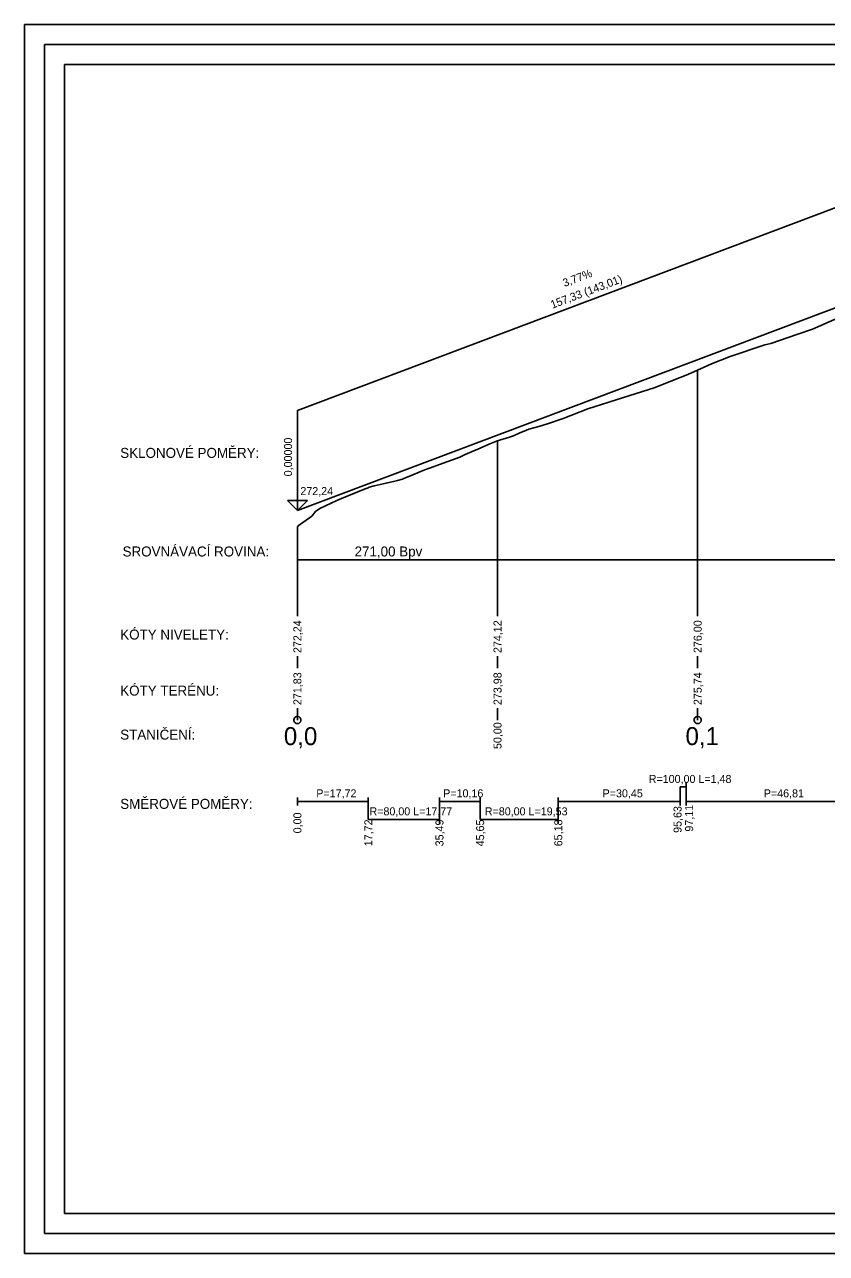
# Model space of a CAD drawing. Extents: x -761995 to -761565, y -1048251 to -1047944.
# Drawn here: x -761994.5 to -761794.2, y -1048251.1 to -1047944.1 of the extents above; entities that cross this region are included whole.
import ezdxf

# ---------------------------------------------------------------- set-up
doc = ezdxf.new("R2010")
doc.units = 0
for name, color, linetype in [('C3D-PROFIL-NIVELETA', 7, 'Continuous'), ('C3D-PROFIL-POPIS', 7, 'Continuous'), ('C3D-PROFIL-POPIS-NIVELETA', 7, 'Continuous'), ('C3D-PROFIL-TEREN', 7, 'Continuous'), ('C3D-ZOBPROF-OSY-NADPIS', 7, 'Continuous'), ('C3D-ZOBPROF-PROUZEK-NAVRH', 7, 'Continuous'), ('C3D-ZOBPROF-PROUZEK-POPIS', 7, 'Continuous'), ('C3D-ZOBPROF-PROUZEK-TEREN', 7, 'Continuous'), ('C3D-ZOBPROF-RASTR-VERHL', 7, 'Continuous'), ('C3D-ZOBPROF-RASTR-VERVEDL', 7, 'Continuous'), ('C3D-ZOBPROF-SROV-ROVINA', 7, 'Continuous'), ('Default', 7, 'Continuous'), ('U_formát', 7, 'Continuous'), ('U_rozvržení_rámeček', 7, 'Continuous')]:
    doc.layers.add(name, color=color, linetype=linetype)

# ---------------------------------------------------------------- blocks, each defined once
blk = doc.blocks.new('PP-sipka')
at = {"layer": 'Default'}
for p, q in [((0, 0), (-4, 4)), ((-4, 4), (4, 4)), ((4, 4), (0, 0))]:
    blk.add_line(p, q, dxfattribs=at)
blk = doc.blocks.new('U1096')
at = {"layer": 'Default'}
for p, q in [((-420, 0), (-420, -10)), ((-420, -297), (-420, -287)), ((-420, -297), (-410, -297))]:
    blk.add_line(p, q, dxfattribs=at)
blk.add_lwpolyline([(0, -297), (0, 0), (-420, 0), (-420, -297)], close=True, dxfattribs=at)
at = {"layer": 'U_formát'}
for points in [[(-425, 5), (5, 5), (5, -302), (-425, -302)], [(-5, -292), (-5, -5), (-415, -5), (-415, -292)]]:
    blk.add_lwpolyline(points, close=True, dxfattribs=at)

msp = doc.modelspace()

# ---------------------------------------------------------------- linework, layer by layer
at = {"layer": 'C3D-PROFIL-NIVELETA'}
msp.add_lwpolyline([(-761926.36, -1048065.48), (-761783.34, -1048011.62)], dxfattribs=at)
at = {"layer": 'C3D-PROFIL-POPIS'}
msp.add_line((-761926.36, -1048069.55), (-761926.36, -1048077.86), dxfattribs=at)
at = {"layer": 'C3D-PROFIL-POPIS-NIVELETA'}
for p, q in [((-761926.36, -1048040.48), (-761783.34, -1047986.62)), ((-761926.36, -1048065.48), (-761926.36, -1048040.48))]:
    msp.add_line(p, q, dxfattribs=at)
at = {"layer": 'C3D-PROFIL-TEREN'}
msp.add_lwpolyline([(-761926.36, -1048069.55), (-761926.16, -1048069.35), (-761922.76, -1048066.89), (-761921.82, -1048065.73), (-761920.76, -1048064.98), (-761916.48, -1048063.02), (-761915.33, -1048062.49), (-761909.4, -1048060.11), (-761908.64, -1048059.81), (-761908.38, -1048059.71), (-761907.2, -1048059.3), (-761906.42, -1048059.13), (-761904.2, -1048058.64), (-761901.97, -1048058.15), (-761901.31, -1048058.01), (-761900.08, -1048057.65), (-761899.75, -1048057.51), (-761897.53, -1048056.57), (-761895.97, -1048055.92), (-761895.31, -1048055.66), (-761894.09, -1048055.18), (-761893.09, -1048054.81), (-761890.87, -1048054.01), (-761885.78, -1048052.18), (-761884.4, -1048051.51), (-761880.71, -1048049.91), (-761878.26, -1048048.86), (-761876.63, -1048048.16), (-761875.82, -1048047.9), (-761873.38, -1048047.14), (-761872.38, -1048046.83), (-761870.94, -1048046.2), (-761869.1, -1048045.39), (-761868.5, -1048045.21), (-761866.06, -1048044.48), (-761863.62, -1048043.74), (-761862.65, -1048043.43), (-761861.18, -1048042.95), (-761859.95, -1048042.54), (-761853.82, -1048040.09), (-761843.28, -1048036.77), (-761837.24, -1048034.82), (-761830.73, -1048032.24), (-761829.25, -1048031.66), (-761827.27, -1048030.88), (-761822.86, -1048028.88), (-761818.23, -1048027.06), (-761809.61, -1048024.11), (-761808.06, -1048023.76), (-761801.56, -1048021.51), (-761797.68, -1048020.19), (-761791.41, -1048017.48)], dxfattribs=at)
at = {"layer": 'C3D-ZOBPROF-PROUZEK-NAVRH'}
for p, q in [((-761830.73, -1048138.16), (-761830.73, -1048134.56)), ((-761830.73, -1048134.56), (-761829.25, -1048134.56)), ((-761829.25, -1048135.56), (-761829.25, -1048133.56)), ((-761829.25, -1048134.56), (-761829.25, -1048138.16)), ((-761926.36, -1048139.16), (-761926.36, -1048137.16)), ((-761908.64, -1048139.16), (-761908.64, -1048137.16)), ((-761890.87, -1048139.16), (-761890.87, -1048137.16)), ((-761880.71, -1048139.16), (-761880.71, -1048137.16)), ((-761861.18, -1048139.16), (-761861.18, -1048137.16)), ((-761830.73, -1048139.16), (-761830.73, -1048137.16)), ((-761829.25, -1048139.16), (-761829.25, -1048137.16)), ((-761926.36, -1048138.16), (-761908.64, -1048138.16)), ((-761908.64, -1048138.16), (-761908.64, -1048142.66)), ((-761890.87, -1048142.66), (-761890.87, -1048138.16)), ((-761890.87, -1048138.16), (-761880.71, -1048138.16)), ((-761880.71, -1048138.16), (-761880.71, -1048142.66)), ((-761861.18, -1048142.66), (-761861.18, -1048138.16)), ((-761861.18, -1048138.16), (-761830.73, -1048138.16)), ((-761829.25, -1048138.16), (-761782.44, -1048138.16)), ((-761908.64, -1048142.66), (-761890.87, -1048142.66)), ((-761890.87, -1048143.66), (-761890.87, -1048141.66)), ((-761880.71, -1048142.66), (-761861.18, -1048142.66)), ((-761861.18, -1048143.66), (-761861.18, -1048141.66))]:
    msp.add_line(p, q, dxfattribs=at)
at = {"layer": 'C3D-ZOBPROF-PROUZEK-POPIS'}
for centre, start, end in [((-761926.36, -1048117.86), 128.6598, 308.6598), ((-761926.36, -1048117.86), 308.6598, 128.6598), ((-761826.36, -1048117.86), 128.6598, 308.6598), ((-761826.36, -1048117.86), 308.6598, 128.6598)]:
    msp.add_arc(centre, 0.89, start, end, dxfattribs=at)
at = {"layer": 'C3D-ZOBPROF-PROUZEK-TEREN'}
for p, q in [((-761926.36, -1048082.86), (-761926.36, -1048077.86)), ((-761876.36, -1048082.86), (-761876.36, -1048077.86)), ((-761826.36, -1048082.86), (-761826.36, -1048077.86)), ((-761926.36, -1048091.86), (-761926.36, -1048082.86)), ((-761876.36, -1048091.86), (-761876.36, -1048082.86)), ((-761826.36, -1048091.86), (-761826.36, -1048082.86)), ((-761926.36, -1048104.86), (-761926.36, -1048101.86)), ((-761876.36, -1048104.86), (-761876.36, -1048101.86)), ((-761826.36, -1048104.86), (-761826.36, -1048101.86)), ((-761926.36, -1048117.86), (-761926.36, -1048114.86)), ((-761876.36, -1048117.86), (-761876.36, -1048114.86)), ((-761826.36, -1048117.86), (-761826.36, -1048114.86))]:
    msp.add_line(p, q, dxfattribs=at)
at = {"layer": 'C3D-ZOBPROF-RASTR-VERHL'}
for p, q in [((-761826.36, -1048077.86), (-761826.36, -1048030.46)), ((-761926.36, -1048077.86), (-761926.36, -1048069.55))]:
    msp.add_line(p, q, dxfattribs=at)
at = {"layer": 'C3D-ZOBPROF-RASTR-VERVEDL'}
msp.add_line((-761876.36, -1048077.86), (-761876.36, -1048048.07), dxfattribs=at)
at = {"layer": 'C3D-ZOBPROF-SROV-ROVINA'}
msp.add_line((-761926.36, -1048077.86), (-761667.03, -1048077.86), dxfattribs=at)

# ---------------------------------------------------------------- block references
at = {"layer": 'C3D-PROFIL-POPIS-NIVELETA', "xscale": 0.625, "yscale": 0.625}
msp.add_blockref('PP-sipka', (-761926.36, -1048065.48), dxfattribs=at)
at = {"layer": 'U_rozvržení_rámeček'}
msp.add_blockref('U1096', (-761569.51, -1047949.1), dxfattribs=at)

# ---------------------------------------------------------------- texts
at = {"layer": 'C3D-PROFIL-POPIS-NIVELETA'}
for s, height, rotation, p in [('3,77%', 2, 20.6359, (-761859.62, -1048009.68)), ('157,33 (143,01)', 2, 20.6359, (-761862.66, -1048015.1)), ('0,00000', 2, 90, (-761927.69, -1048056.96)), ('SKLONOVÉ POMĚRY:', 2.5, 360, (-761970.61, -1048052.36))]:
    msp.add_text(s, height=height, rotation=rotation, dxfattribs=at).set_placement(p)
msp.add_text('272,24', height=2, dxfattribs=at).set_placement((-761925.61, -1048061.65))
at = {"layer": 'C3D-ZOBPROF-OSY-NADPIS'}
msp.add_text('SROVNÁVACÍ ROVINA:                       271,00 Bpv', height=2.5, dxfattribs=at).set_placement((-761970.02, -1048076.99))
at = {"layer": 'C3D-ZOBPROF-PROUZEK-NAVRH'}
for s, height, p in [('R=100,00 L=1,48', 2, (-761838.58, -1048133.56)), ('SMĚROVÉ POMĚRY:', 2.5, (-761970.61, -1048140.04)), ('P=17,72', 2, (-761921.63, -1048137.16)), ('P=10,16', 2, (-761889.93, -1048137.16)), ('P=30,45', 2, (-761850.1, -1048137.16)), ('P=46,81', 2, (-761809.83, -1048137.16)), ('R=80,00 L=17,77', 2, (-761908.34, -1048141.66)), ('R=80,00 L=19,53', 2, (-761879.53, -1048141.66))]:
    msp.add_text(s, height=height, dxfattribs=at).set_placement(p)
for s, p in [('95,63', (-761830.38, -1048146.04)), ('97,11', (-761827.49, -1048145.73)), ('0,00', (-761925.35, -1048146.15)), ('17,72', (-761907.63, -1048149.38)), ('35,49', (-761889.86, -1048149.4)), ('45,65', (-761879.7, -1048149.41)), ('65,18', (-761860.17, -1048149.4))]:
    msp.add_text(s, height=2, rotation=90, dxfattribs=at).set_placement(p)
at = {"layer": 'C3D-ZOBPROF-PROUZEK-POPIS'}
for s, p in [('0,0', (-761929.73, -1048124.12)), ('0,1', (-761829.39, -1048124.12))]:
    msp.add_text(s, height=4.5, dxfattribs=at).set_placement(p)
at = {"layer": 'C3D-ZOBPROF-PROUZEK-TEREN'}
for s, p in [('KÓTY NIVELETY:', (-761970.61, -1048097.74)), ('KÓTY TERÉNU:', (-761970.61, -1048111.74)), ('STANIČENÍ:', (-761970.61, -1048122.74))]:
    msp.add_text(s, height=2.5, dxfattribs=at).set_placement(p)
for s, p in [('272,24', (-761925.35, -1048101.11)), ('274,12', (-761875.35, -1048101.11)), ('276,00', (-761825.35, -1048101.11)), ('271,83', (-761925.35, -1048114.11)), ('273,98', (-761875.35, -1048114.11)), ('275,74', (-761825.35, -1048114.11)), ('50,00', (-761875.35, -1048125.09))]:
    msp.add_text(s, height=2, rotation=90, dxfattribs=at).set_placement(p)

doc.saveas('drawing.dxf')
